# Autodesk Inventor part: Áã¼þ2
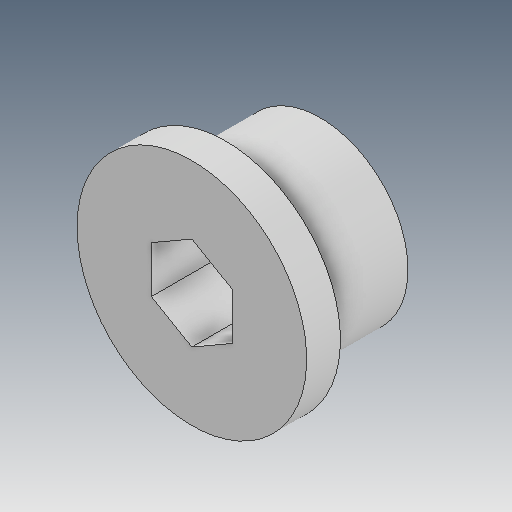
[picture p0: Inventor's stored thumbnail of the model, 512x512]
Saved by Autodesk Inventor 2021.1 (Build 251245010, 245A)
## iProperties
Created: 2014-12
Part Number: Áã¼þ2
Material: Ogólny
Document SubType Name: Modeling
Designer: user
Density: 1 g/cm^3
Appearance: Domyślna
Author: user
Revision Number: ÈÎºÎ
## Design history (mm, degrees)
feature "ÇÐ³ý-À­Éì1"
node "Bryła1"
